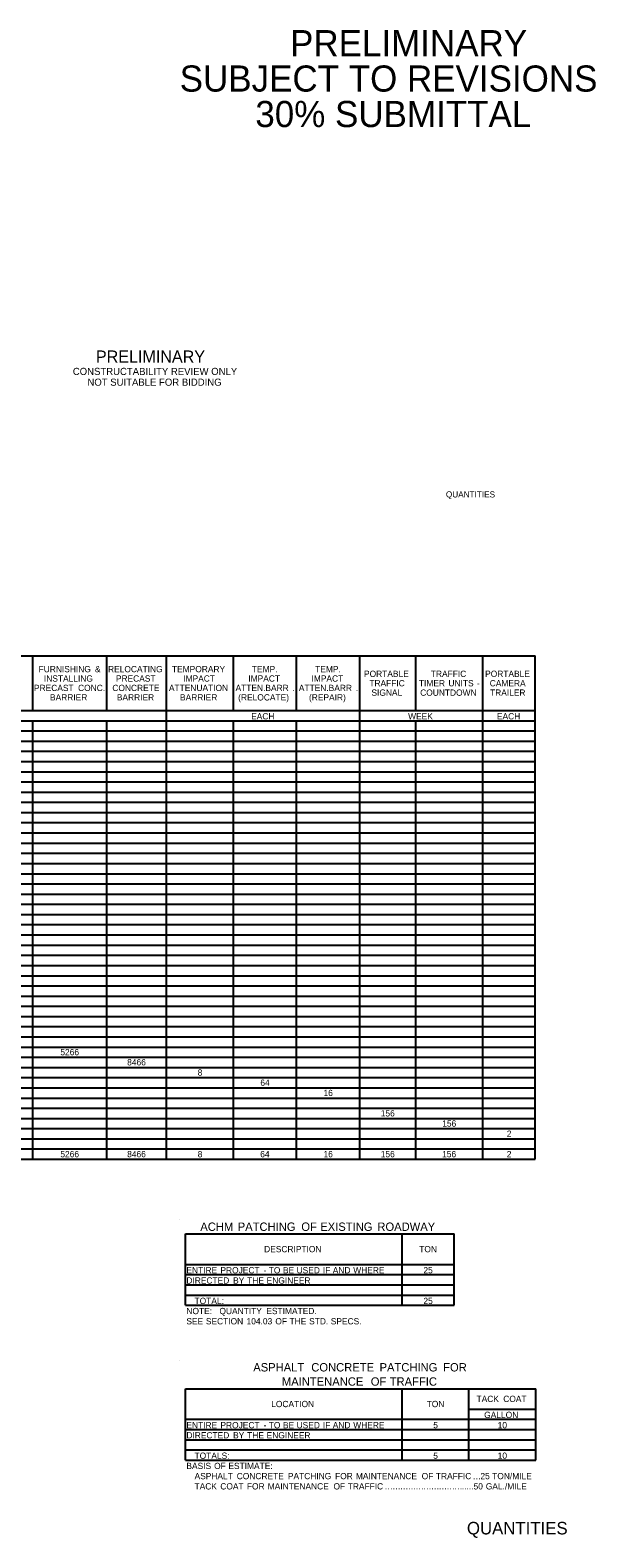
# Model space of a CAD drawing. Extents: x 107 to 7866, y 32 to 1473.
# Drawn here: x 1143 to 1683, y 32 to 1473 of the extents above; entities that cross this region are included whole.
import ezdxf

# ---------------------------------------------------------------- set-up
doc = ezdxf.new("R2010")
doc.units = 0
for name, color, linetype in [('B_Concrete', 7, 'Continuous'), ('Default', 7, 'Continuous'), ('R_Annotation', 7, 'Continuous'), ('R_Border', 7, 'Continuous'), ('R_Draft', 7, 'Continuous'), ('R_No Plot', 7, 'Continuous')]:
    doc.layers.add(name, color=color, linetype=linetype)

msp = doc.modelspace()

# ---------------------------------------------------------------- linework, layer by layer
at = {"layer": 'Default'}
for p, q in [((112.8, 874.7), (1625.5, 874.7)), ((1145.3, 822.5), (1145.3, 874.7)), ((1216, 822.5), (1216, 874.7)), ((1273.1, 393.5), (1273.1, 874.7)), ((1336.9, 822.5), (1336.9, 874.7)), ((1397.4, 822.5), (1397.4, 874.7)), ((1457.8, 393.5), (1457.8, 874.7)), ((1511.4, 822.5), (1511.4, 874.7)), ((1575.3, 393.5), (1575.3, 874.7)), ((1625.5, 393.5), (1625.5, 874.7)), ((670, 822.5), (1625.5, 822.5)), ((955.7, 822.5), (1273.1, 822.5)), ((1273.1, 822.5), (1511.4, 822.5)), ((1273.1, 500.8), (1273.1, 822.5)), ((1457.8, 812.8), (1457.8, 822.5)), ((1511.4, 822.5), (1625.5, 822.5)), ((112.8, 812.8), (1625.5, 812.8)), ((619.8, 812.8), (1625.5, 812.8)), ((1145.3, 500.8), (1145.3, 812.8)), ((1145.3, 393.5), (1145.3, 812.8)), ((1216, 393.5), (1216, 812.8)), ((1216, 393.5), (1216, 812.8)), ((1336.9, 393.5), (1336.9, 812.8)), ((1336.9, 393.5), (1336.9, 812.8)), ((1397.4, 393.5), (1397.4, 812.8)), ((1397.4, 393.5), (1397.4, 812.8)), ((1511.4, 393.5), (1511.4, 812.8)), ((112.8, 803), (1625.5, 803)), ((112.8, 793.3), (1625.5, 793.3)), ((112.8, 783.5), (1625.5, 783.5)), ((112.8, 773.8), (1625.5, 773.8)), ((112.8, 764), (1625.5, 764)), ((112.8, 754.3), (1625.5, 754.3)), ((112.8, 744.5), (1625.5, 744.5)), ((112.8, 734.8), (1625.5, 734.8)), ((112.8, 725), (1625.5, 725)), ((112.8, 715.3), (1625.5, 715.3)), ((112.8, 705.5), (1625.5, 705.5)), ((112.8, 695.8), (1625.5, 695.8)), ((112.8, 686), (1625.5, 686)), ((112.8, 676.3), (1625.5, 676.3)), ((112.8, 666.5), (1625.5, 666.5)), ((112.8, 656.8), (1625.5, 656.8)), ((112.8, 647), (1625.5, 647)), ((112.8, 637.3), (1625.5, 637.3)), ((112.8, 627.5), (1625.5, 627.5)), ((112.8, 617.8), (1625.5, 617.8)), ((112.8, 608), (1625.5, 608)), ((112.8, 598.3), (1625.5, 598.3)), ((112.8, 588.5), (1625.5, 588.5)), ((112.8, 578.8), (1625.5, 578.8)), ((112.8, 569), (1625.5, 569)), ((112.8, 559.3), (1625.5, 559.3)), ((112.8, 549.5), (1625.5, 549.5)), ((112.8, 539.8), (1625.5, 539.8)), ((112.8, 530), (1625.5, 530)), ((112.8, 520.3), (1625.5, 520.3)), ((112.8, 510.5), (1625.5, 510.5)), ((112.8, 500.8), (1625.5, 500.8)), ((112.8, 491), (1625.5, 491)), ((1074.6, 500.8), (1145.3, 500.8)), ((1074.6, 491), (1273.1, 491)), ((1145.3, 500.8), (1273.1, 500.8)), ((1145.3, 393.5), (1145.3, 491)), ((1273.1, 500.8), (1511.4, 500.8)), ((1273.1, 491), (1511.4, 491)), ((1273.1, 422.8), (1273.1, 491)), ((1511.4, 500.8), (1625.5, 500.8)), ((1511.4, 491), (1625.5, 491)), ((112.8, 481.3), (1625.5, 481.3)), ((112.8, 471.5), (1625.5, 471.5)), ((112.8, 461.8), (1625.5, 461.8)), ((112.8, 452), (1625.5, 452)), ((112.8, 442.3), (1625.5, 442.3)), ((112.8, 432.5), (1625.5, 432.5)), ((112.8, 422.8), (1625.5, 422.8)), ((112.8, 413), (1625.5, 413)), ((670, 413), (1625.5, 413)), ((1273.1, 393.5), (1273.1, 413)), ((112.8, 403.3), (1625.5, 403.3)), ((112.8, 393.5), (1625.5, 393.5)), ((1291.1, 322.2), (1548, 322.2)), ((1291.1, 253.9), (1291.1, 322.2)), ((1291.1, 253.9), (1291.1, 322.2)), ((1498.2, 253.9), (1498.2, 322.2)), ((1548, 253.9), (1548, 322.2)), ((1291.1, 292.9), (1548, 292.9)), ((1498.2, 253.9), (1498.2, 292.9)), ((1548, 253.9), (1548, 292.9)), ((1291.1, 283.2), (1548, 283.2)), ((1291.1, 273.4), (1548, 273.4)), ((1291.1, 263.7), (1548, 263.7)), ((1291.1, 253.9), (1548, 253.9)), ((1285.2, 201.4), (1285.2, 201.4)), ((1291.1, 174.1), (1626, 174.1)), ((1291.1, 105.9), (1291.1, 174.1)), ((1291.1, 105.9), (1291.1, 174.1)), ((1498.2, 105.9), (1498.2, 174.1)), ((1562.1, 105.9), (1562.1, 174.1)), ((1626, 105.9), (1626, 174.1)), ((1626, 154.6), (1626, 174.1)), ((1291.1, 144.9), (1626, 144.9)), ((1498.2, 105.9), (1498.2, 144.9)), ((1562.1, 154.6), (1626, 154.6)), ((1562.1, 105.9), (1562.1, 154.6)), ((1626, 125.4), (1626, 144.9)), ((1291.1, 135.1), (1626, 135.1)), ((1291.1, 125.4), (1626, 125.4)), ((1291.1, 115.6), (1626, 115.6)), ((1626, 105.9), (1626, 115.6)), ((1291.1, 105.9), (1626, 105.9))]:
    msp.add_line(p, q, dxfattribs=at)
at = {"layer": 'R_No Plot'}
msp.add_line((1285.2, 335.8), (1285.2, 335.8), dxfattribs=at)

# ---------------------------------------------------------------- texts
at = {"layer": 'B_Concrete'}
for s, p in [('PRELIMINARY', (1391.1, 1448)), ('SUBJECT TO REVISIONS', (1285.6, 1414.2)), ('30% SUBMITTAL', (1357.9, 1380.3))]:
    msp.add_text(s, height=25, dxfattribs=at).set_placement(p)
at = {"layer": 'Default'}
for s, height, p in [('FURNISHING', 6, (1150.7, 859.1)), (' &', 6, (1202.4, 859.1)), ('RELOCATING', 6, (1217.1, 859.1)), ('TEMPORARY', 6, (1278.2, 859.1)), ('TEMP.', 6, (1354.6, 859.1)), ('TEMP.', 6, (1415.1, 859.1)), ('INSTALLING', 6, (1155.8, 850.1)), ('PRECAST', 6, (1224.6, 850.1)), ('IMPACT', 6, (1289, 850.1)), ('IMPACT', 6, (1351.2, 850.1)), ('IMPACT', 6, (1411.6, 850.1)), ('PORTABLE', 6, (1461.8, 854.6)), ('TRAFFIC', 6, (1466.9, 845.6)), ('TIMER', 6, (1514.3, 845.6)), ('TRAFFIC', 6, (1525.7, 854.6)), (' UNITS', 6, (1540.3, 845.6)), ('PORTABLE', 6, (1577.6, 854.6)), ('CAMERA', 6, (1582, 845.6)), ('PRECAST', 6, (1146.3, 841.1)), ('BARRIER', 6, (1161.6, 832.1)), (' CONC.', 6, (1186.2, 841.1)), ('CONCRETE', 6, (1221.2, 841.1)), ('BARRIER', 6, (1225.5, 832.1)), ('ATTENUATION', 6, (1275.3, 841.1)), ('BARRIER', 6, (1285.9, 832.1)), ('ATTEN.BARR', 6, (1339, 841.1)), ('(RELOCATE)', 6, (1341.5, 832.1)), ('.', 6, (1393.5, 841.1)), ('ATTEN.BARR', 6, (1399.5, 841.1)), ('(REPAIR)', 6, (1409.2, 832.1)), ('.', 6, (1453.9, 841.1)), ('SIGNAL', 6, (1468.9, 836.6)), ('COUNTDOWN', 6, (1515.5, 836.6)), (' -', 6, (1567.4, 845.6)), ('TRAILER', 6, (1582.3, 836.6)), ('EACH', 6, (1353.9, 814)), ('WEEK', 6, (1504, 814)), ('EACH', 6, (1588.9, 814)), ('5266', 6, (1171.5, 492.9)), ('8466', 6, (1235.4, 483.2)), ('8', 6, (1302.8, 473.4)), ('64', 6, (1362.7, 463.7)), ('16', 6, (1423.1, 453.9)), ('156', 6, (1477.8, 434.4)), ('156', 6, (1536.6, 424.7)), ('2', 6, (1598.3, 414.9)), ('5266', 6, (1171.5, 395.4)), ('8466', 6, (1235.4, 395.4)), ('8', 6, (1302.8, 395.4)), ('64', 6, (1362.6, 395.4)), ('16', 6, (1423.1, 395.4)), ('156', 6, (1477.8, 395.4)), ('156', 6, (1536.5, 395.4)), ('2', 6, (1598.3, 395.4)), ('ACHM', 8, (1305.3, 325)), (' PATCHING', 8, (1338.1, 325)), (' OF', 8, (1398.9, 325)), (' EXISTING', 8, (1417, 325)), (' ROADWAY', 8, (1471.6, 325)), ('DESCRIPTION', 6, (1366.3, 304.6)), ('TON', 6, (1514.6, 304.6)), ('ENTIRE', 6, (1292, 284.4)), (' PROJECT', 6, (1322.3, 284.4)), (' TO', 6, (1368.5, 284.4)), (' BE', 6, (1382.1, 284.4)), (' USED', 6, (1395.1, 284.4)), (' IF', 6, (1420.3, 284.4)), (' AND', 6, (1429.7, 284.4)), (' WHERE', 6, (1449.3, 284.4)), ('25', 6, (1518.6, 284.4)), ('DIRECTED', 6, (1292, 274.6)), (' BY', 6, (1334.4, 274.6)), (' THE', 6, (1347.9, 274.6)), (' -', 6, (1363.6, 284.4)), (' ENGINEER', 6, (1366.5, 274.6)), ('TOTAL:', 6, (1299.8, 255.1)), ('25', 6, (1518.6, 255.1)), ('NOTE:', 6, (1292, 245.4)), ('   QUANTITY', 6, (1316.9, 245.4)), (' ESTIMATED.', 6, (1366.2, 245.4)), ('SEE', 6, (1292, 235.6)), (' SECTION', 6, (1308.4, 235.6)), (' 104.03', 6, (1347.3, 235.6)), (' OF', 6, (1374.8, 235.6)), (' THE', 6, (1388.4, 235.6)), (' STD.', 6, (1407.1, 235.6)), (' SPECS.', 6, (1427.8, 235.6)), ('ASPHALT', 8, (1355.9, 190.6)), (' CONCRETE', 8, (1408.4, 190.6)), (' PATCHING', 8, (1473.7, 190.6)), (' FOR', 8, (1534.5, 190.6)), ('MAINTENANCE', 8, (1383.3, 177)), (' OF', 8, (1465.3, 177)), (' TRAFFIC', 8, (1483.4, 177)), ('LOCATION', 6, (1373.1, 156.5)), ('TON', 6, (1521.7, 156.5)), ('TACK', 6, (1569.4, 161.4)), (' COAT', 6, (1592.7, 161.4)), ('GALLON', 6, (1576.7, 146.1)), ('ENTIRE', 6, (1292, 136.3)), ('DIRECTED', 6, (1292, 126.6)), (' PROJECT', 6, (1322.3, 136.3)), (' BY', 6, (1334.4, 126.6)), (' THE', 6, (1347.9, 126.6)), (' -', 6, (1363.6, 136.3)), (' ENGINEER', 6, (1366.5, 126.6)), (' TO', 6, (1368.5, 136.3)), (' BE', 6, (1382.1, 136.3)), (' USED', 6, (1395.1, 136.3)), (' IF', 6, (1420.3, 136.3)), (' AND', 6, (1429.7, 136.3)), (' WHERE', 6, (1449.3, 136.3)), ('5', 6, (1528, 136.3)), ('10', 6, (1589.6, 136.3)), ('BASIS', 6, (1292, 97.3)), ('TOTALS:', 6, (1299.8, 107.1)), (' OF', 6, (1316.3, 97.3)), (' ESTIMATE:', 6, (1329.9, 97.3)), ('5', 6, (1528, 107.1)), ('10', 6, (1589.6, 107.1)), ('ASPHALT', 6, (1299.8, 87.6)), (' CONCRETE', 6, (1337.9, 87.6)), (' PATCHING', 6, (1386.8, 87.6)), (' FOR', 6, (1431.9, 87.6)), (' MAINTENANCE', 6, (1451.8, 87.6)), (' OF', 6, (1514.7, 87.6)), (' TRAFFIC', 6, (1528.3, 87.6)), ('…', 6, (1565.7, 87.6)), ('25', 6, (1573.1, 87.6)), (' TON/MILE', 6, (1582.1, 87.6)), ('TACK', 6, (1299.8, 77.8)), (' COAT', 6, (1322.2, 77.8)), (' FOR', 6, (1347.6, 77.8)), (' MAINTENANCE', 6, (1367.5, 77.8)), (' OF', 6, (1430.4, 77.8)), (' TRAFFIC', 6, (1444, 77.8)), ('…', 6, (1481.4, 77.8)), ('…', 6, (1488.8, 77.8)), ('…', 6, (1496.2, 77.8)), ('…', 6, (1503.6, 77.8)), ('…', 6, (1511, 77.8)), ('…', 6, (1518.4, 77.8)), ('…', 6, (1525.8, 77.8)), ('…', 6, (1533.2, 77.8)), ('…', 6, (1540.6, 77.8)), ('…', 6, (1548, 77.8)), ('.....50', 6, (1555.4, 77.8)), (' GAL./MILE', 6, (1576, 77.8))]:
    msp.add_text(s, height=height, dxfattribs=at).set_placement(p)
at = {"layer": 'R_Annotation'}
msp.add_text('QUANTITIES', height=12, rotation=360, dxfattribs=at).set_placement((1560.2, 34.8))
at = {"layer": 'R_Border'}
msp.add_text('QUANTITIES', height=5.86, dxfattribs=at).set_placement((1540.1, 1026.2))
at = {"layer": 'R_Draft'}
for s, height, p in [('PRELIMINARY', 11.508, (1205.5, 1155.2)), ('CONSTRUCTABILITY REVIEW ONLY', 6.823, (1183.4, 1143.3)), ('NOT SUITABLE FOR BIDDING', 6.823, (1197.4, 1133))]:
    msp.add_text(s, height=height, rotation=0, dxfattribs=at).set_placement(p)

doc.saveas('drawing.dxf')
